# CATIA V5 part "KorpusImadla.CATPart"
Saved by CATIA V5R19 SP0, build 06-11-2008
Part number: Korpus imadła
Revision: ANY
Definition: SW3dPS-49472SC
Source: Unknown
Bounding box of the stored display mesh (mm): x -114.3 to 114.3, y 0 to 122.377, z -254 to 322.275
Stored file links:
  D:\POBO\catia\test\Imadło\KorpusImadla.CATPart
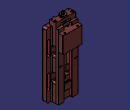
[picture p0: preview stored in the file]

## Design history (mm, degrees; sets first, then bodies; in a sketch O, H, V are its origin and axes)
Body1 "Body" (main body)
  Solid1 "Manifold Solid #24700": solid without history
  Body2 "718112-1-solid1"
    Solid2 "Manifold Solid #24712": solid without history
  Add1: tool Body2
  Body3 "718112-2-solid1"
    Solid3 "Manifold Solid #24714": solid without history
  Add2: tool Body3
  Body4 "718494-1-solid1"
    Solid4 "Manifold Solid #24713": solid without history
  Add3: tool Body4
  Body5 "718132-1-solid1"
    Solid5 "Manifold Solid #24723": solid without history
  Add4: tool Body5
  Body6 "718330-2-solid1"
    Solid6 "Manifold Solid #24707": solid without history
  Add5: tool Body6
  Body7 "718132-2-solid1"
    Solid7 "Manifold Solid #24710": solid without history
  Add6: tool Body7
  Body8 "718326-1-solid1"
    Solid8 "Manifold Solid #24708": solid without history
  Add7: tool Body8
  Body9 "718326-2-solid1"
    Solid9 "Manifold Solid #24705": solid without history
  Add8: tool Body9
  Body10 "718523GIB-1/718582-1-solid1"
    Solid10 "Manifold Solid #24706": solid without history
  Add9: tool Body10
  Body11 "718523GIB-1/718479-1-solid1"
    Solid11 "Manifold Solid #24703": solid without history
  Add10: tool Body11
  Body12 "718523GIB-1/718479-2-solid1"
    Solid12 "Manifold Solid #24702": solid without history
  Add11: tool Body12
  Body13 "718523GIB-2/718479-1-solid1"
    Solid13 "Manifold Solid #24717": solid without history
  Add12: tool Body13
  Body14 "718523GIB-2/718479-2-solid1"
    Body15 "718209-A-1/718213-1-solid1"
      Solid14 "Manifold Solid #24719": solid without history
    Add13: tool Body15
    Body16 "718209-A-1/718215-1-solid1"
      Solid15 "Manifold Solid #24711": solid without history
    Add14: tool Body16
    Body17 "718209-A-1/718126-2-solid1"
      Solid16 "Manifold Solid #24704": solid without history
    Add15: tool Body17
    Body18 "718490-1/718493-1-solid1"
      Solid17 "Manifold Solid #24720": solid without history
    Add16: tool Body18
    Body19 "718490-1/718491-1-solid1"
      Solid18 "Manifold Solid #24715": solid without history
    Add17: tool Body19
    Body20 "718490-1/718492-1-solid1"
      Solid19 "Manifold Solid #24722": solid without history
    Add18: tool Body20
    Body21 "718490-1/718325-1-solid1"
    Add19: tool Body21
    Body22 "718490-1/718323-1-solid1"
      Solid20 "Manifold Solid #24721": solid without history
    Add20: tool Body22
    Body23 "718490-1/718323-2-solid1"
      Solid21 "Manifold Solid #24718": solid without history
    Add21: tool Body23
  Add22: tool Body14
  Sketch1 on face of Solid1, origin (0, 31.75, 0), H (-1, 0, 0), V (0, 0, 1)
    line L1 (-112.5478, -184.4524) -> (-87.748, -184.4524)
    line L2 (-87.748, -184.4524) -> (-87.748, -217.9279)
    line L3 (-87.748, -217.9279) -> (-112.5478, -217.9279)
    line L4 (-112.5478, -217.9279) -> (-112.5478, -184.4524)
    horizontal: L1 H, L3 H
    vertical: L2 V, L4 V
  Pad1: profile Sketch1, direction (0, -1, 0), length 20
  Sketch2 on face of Pad1, origin (0, 31.75, 0), H (-1, 0, 0), V (0, 0, 1)
    line L1 (-114.1238, 13.49) -> (-84.9107, 13.49)
    line L2 (-84.9107, 13.49) -> (-84.9107, -15.3839)
    line L3 (-84.9107, -15.3839) -> (-114.1238, -15.3839)
    line L4 (-114.1238, -15.3839) -> (-114.1238, 13.49)
    point P5 (85.0213, 13.49)
    line L5 (85.0213, 13.49) -> (111.5612, 13.49)
    line L6 (111.5612, 13.49) -> (111.5612, -15.3839)
    line L7 (111.5612, -15.3839) -> (85.0213, -15.3839)
    line L8 (85.0213, -15.3839) -> (85.0213, 13.49)
    point P7 (111.5612, -15.3839)
    line L9 (86.085, -185.5681) -> (111.0975, -185.5681)
    line L10 (111.0975, -185.5681) -> (111.0975, -214.8244)
    line L11 (111.0975, -214.8244) -> (86.085, -214.8244)
    line L12 (86.085, -214.8244) -> (86.085, -185.5681)
    line L13 (-112.5932, 213.8866) -> (-86.626, 213.8866)
    line L14 (-86.626, 213.8866) -> (-86.626, 185.5863)
    line L15 (-86.626, 185.5863) -> (-112.5932, 185.5863)
    line L16 (-112.5932, 185.5863) -> (-112.5932, 213.8866)
    line L17 (84.4516, 215.7988) -> (111.1825, 215.7988)
    line L18 (111.1825, 215.7988) -> (111.1825, 185.5863)
    line L19 (111.1825, 185.5863) -> (84.4516, 185.5863)
    line L20 (84.4516, 185.5863) -> (84.4516, 215.7988)
    point P19 (111.1825, 185.5863)
    horizontal: L1 H, L3 H, L5 H, L7 H, L9 H, L11 H, L13 H, L15 H, L17 H, L19 H
    vertical: L2 V, L4 V, L6 V, L8 V, L10 V, L12 V, L14 V, L16 V, L18 V, L20 V
    coincidence: P5 L1, P7 L3, P19 L15
  Pad2: profile Sketch2, direction (0, -1, 0), length 20
  Chamfer1: length 4, angle 45, on edge [face of Solid10 | face of Solid10]
  Chamfer2: length 4, angle 45, on edge [face of Solid10 | face of Solid10]
  Sketch3 on face of Solid1, origin (76.2, 0, 0), H (0, 1, 0), V (0, 0, 1)
    line L1 (42.7873, 27.6806) -> (59.3667, 27.6806)
    line L2 (59.3667, 27.6806) -> (59.3667, -29.0945)
    line L3 (59.3667, -29.0945) -> (42.7873, -29.0945)
    line L4 (42.7873, -29.0945) -> (42.7873, 27.6806)
    horizontal: L1 H, L3 H
    vertical: L2 V, L4 V
  Pad3: profile Sketch3, direction (-1, 0, 0), length 3
  Sketch4 on face of Solid1, origin (-76.2, 0, 0), H (0, -1, 0), V (0, 0, 1)
    line L1 (-61.1944, 27.805) -> (-41.132, 27.805)
    line L2 (-41.132, 27.805) -> (-41.132, -30.6685)
    line L3 (-41.132, -30.6685) -> (-61.1944, -30.6685)
    line L4 (-61.1944, -30.6685) -> (-61.1944, 27.805)
    horizontal: L1 H, L3 H
    vertical: L2 V, L4 V
  Pad4: profile Sketch4, direction (1, 0, 0), length 3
